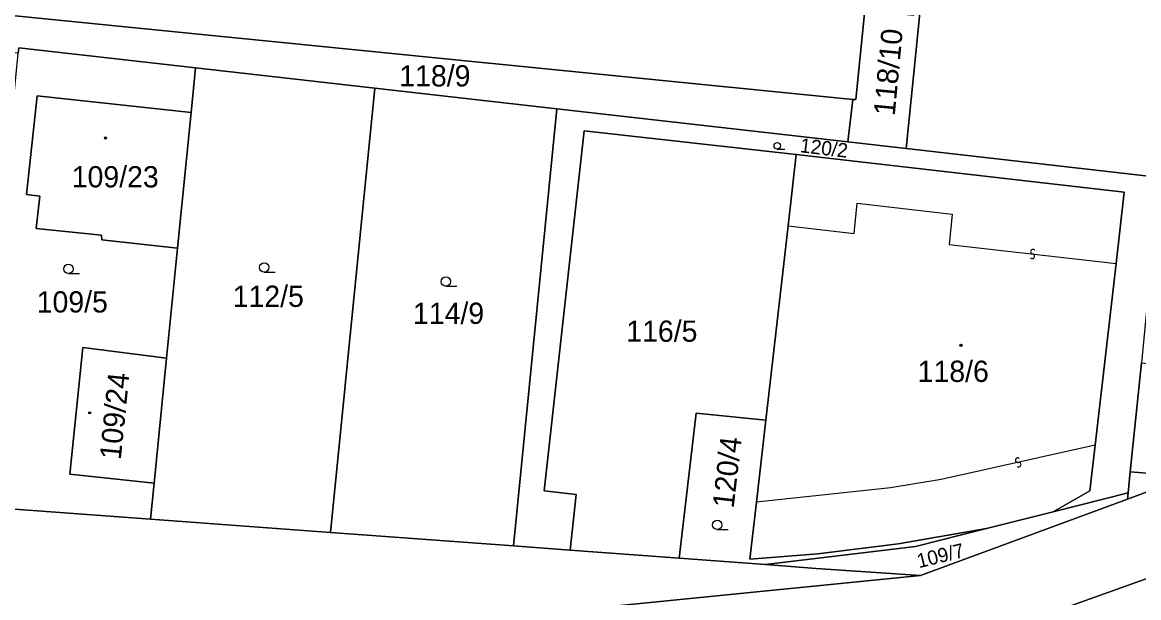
# Model space of a CAD drawing. Extents: x -598233 to -596890, y -1157848 to -1156431.
# Drawn here: x -597800.5 to -597711.3, y -1156974 to -1156928 of the extents above; entities that cross this region are included whole.
import ezdxf

# ---------------------------------------------------------------- set-up
doc = ezdxf.new("R2010")
doc.units = 0
for name, color, linetype in [('Level 1', 7, 'Continuous'), ('Level 13', 7, 'Continuous'), ('Level 3', 7, 'Continuous'), ('Level 4', 7, 'Continuous'), ('Level 5', 7, 'Continuous'), ('Level 60', 7, 'Continuous')]:
    doc.layers.add(name, color=color, linetype=linetype)

msp = doc.modelspace()

# ---------------------------------------------------------------- linework, layer by layer
at = {"layer": 'Level 1'}
for points in [[(-597727.02, -1156909.5), (-597729.1, -1156930.44), (-597729.86, -1156938.05)], [(-597734.12, -1156934.12), (-597811.53, -1156926.41)], [(-597733.17, -1156927), (-597733.89, -1156934.14), (-597734.12, -1156934.12)], [(-597786.67, -1156931.6), (-597800.79, -1156930), (-597800.83, -1156930.42)], [(-597786.67, -1156931.6), (-597787.02, -1156935.17)], [(-597772.34, -1156933.23), (-597786.67, -1156931.6)], [(-597775.87, -1156968.75), (-597772.34, -1156933.23)], [(-597757.78, -1156934.88), (-597772.34, -1156933.23)], [(-597788.1, -1156946.01), (-597794.16, -1156945.36), (-597794.17, -1156944.98), (-597799.41, -1156944.45), (-597799.11, -1156941.86), (-597800.18, -1156941.72), (-597799.33, -1156933.85), (-597787.02, -1156935.17)], [(-597734.12, -1156934.12), (-597734.53, -1156937.52)], [(-597787.02, -1156935.17), (-597788.1, -1156946.01)], [(-597757.78, -1156934.88), (-597761.25, -1156969.82)], [(-597734.53, -1156937.52), (-597757.78, -1156934.88)], [(-597738.67, -1156938.54), (-597755.61, -1156936.64), (-597758.79, -1156965.41), (-597756.25, -1156965.7), (-597756.73, -1156970.15)], [(-597734.53, -1156937.52), (-597729.86, -1156938.05)], [(-597740.42, -1156982.59), (-597736.99, -1156981.86), (-597702.06, -1156969.37), (-597691.71, -1156965.31), (-597650.91, -1156948.42), (-597627.87, -1156938.26)], [(-597738.67, -1156938.54), (-597739.31, -1156944.24)], [(-597713.09, -1156947.25), (-597712.44, -1156941.54), (-597738.67, -1156938.54)], [(-597709.57, -1156940.36), (-597729.86, -1156938.05)], [(-597739.31, -1156944.24), (-597741.07, -1156959.76)], [(-597788.1, -1156946.01), (-597788.97, -1156954.81)], [(-597714.75, -1156961.76), (-597713.09, -1156947.25)], [(-597789.96, -1156964.79), (-597796.72, -1156964.08), (-597795.67, -1156953.97), (-597788.97, -1156954.81)], [(-597788.97, -1156954.81), (-597789.96, -1156964.79)], [(-597711.96, -1156963.9), (-597711.07, -1156955.17)], [(-597748.02, -1156970.8), (-597746.64, -1156959.21), (-597741.07, -1156959.76)], [(-597741.07, -1156959.76), (-597741.83, -1156966.31)], [(-597718.13, -1156967.08), (-597715.18, -1156965.42), (-597714.75, -1156961.76)], [(-597712.13, -1156965.57), (-597711.96, -1156963.9)], [(-597711.96, -1156963.9), (-597707.29, -1156964.27)], [(-597789.96, -1156964.79), (-597790.25, -1156967.68)], [(-597712.18, -1156966.07), (-597707.29, -1156964.27)], [(-597718.13, -1156967.08), (-597712.13, -1156965.57)], [(-597712.18, -1156966.07), (-597712.13, -1156965.57)], [(-597741.83, -1156966.31), (-597742.35, -1156970.87), (-597736.93, -1156970.45), (-597730.5, -1156969.64), (-597723.45, -1156968.43)], [(-597728.72, -1156972.17), (-597712.18, -1156966.07)], [(-597804.41, -1156966.64), (-597790.25, -1156967.68)], [(-597723.45, -1156968.43), (-597718.13, -1156967.08)], [(-597790.25, -1156967.68), (-597775.87, -1156968.75)], [(-597775.87, -1156968.75), (-597761.25, -1156969.82)], [(-597741.12, -1156971.31), (-597729.13, -1156969.86), (-597723.45, -1156968.43)], [(-597761.25, -1156969.82), (-597756.73, -1156970.15)], [(-597756.73, -1156970.15), (-597748.02, -1156970.8)], [(-597748.02, -1156970.8), (-597741.12, -1156971.31)], [(-597728.72, -1156972.17), (-597737.05, -1156971.61), (-597741.12, -1156971.31)], [(-597728.72, -1156972.17), (-597771.93, -1156976.51), (-597816.86, -1156986.47), (-597833.49, -1156992.82)]]:
    msp.add_lwpolyline(points, dxfattribs=at)
at = {"layer": 'Level 13'}
for centre, start, end in [((-597719.782, -1156946.663), 210.62032, 83.21032), ((-597719.737, -1156946.297), 30.83478, 262.93277), ((-597720.949, -1156962.96), 49.74124, 282.33124), ((-597720.871, -1156963.32), 229.9557, 102.05369)]:
    msp.add_arc(centre, 0.184, start, end, dxfattribs=at)
at = {"layer": 'Level 3'}
for points in [[(-597739.31, -1156944.24), (-597734.03, -1156944.85), (-597733.78, -1156942.41), (-597726.18, -1156943.29), (-597726.44, -1156945.72), (-597713.09, -1156947.25)], [(-597714.75, -1156961.76), (-597727.07, -1156964.51), (-597731.12, -1156965.18), (-597741.83, -1156966.31)]]:
    msp.add_lwpolyline(points, dxfattribs=at)
at = {"layer": 'Level 5'}
for p, q in [((-597740.17, -1156938.09), (-597739.575, -1156938.09)), ((-597796.82, -1156948.05), (-597795.945, -1156948.05)), ((-597781.17, -1156947.93), (-597780.295, -1156947.93)), ((-597766.65, -1156949.06), (-597765.775, -1156949.06)), ((-597744.97, -1156968.51), (-597744.095, -1156968.51))]:
    msp.add_line(p, q, dxfattribs=at)
for centre, radius in [((-597793.86, -1156937.22), 0.09), ((-597793.86, -1156937.22), 0.0521), ((-597740.17, -1156937.835), 0.255), ((-597796.82, -1156947.675), 0.375), ((-597781.17, -1156947.555), 0.375), ((-597766.65, -1156948.685), 0.375), ((-597725.49, -1156953.78), 0.09), ((-597725.49, -1156953.78), 0.0521), ((-597795.13, -1156959.18), 0.09), ((-597795.13, -1156959.18), 0.0521), ((-597744.97, -1156968.135), 0.375)]:
    msp.add_circle(centre, radius, dxfattribs=at)
at = {"layer": 'Level 60'}
for points in [[(-597728.06, -1156901.77), (-597726.35, -1156886.79), (-597702.27, -1156890.36), (-597704.74, -1156904.94), (-597709.45, -1156932.7), (-597709.6, -1156933.62), (-597708.92, -1156933.7), (-597709.57, -1156940.36), (-597729.86, -1156938.05), (-597729.1, -1156930.44), (-597727.02, -1156909.5), (-597728.59, -1156906.36)], [(-597732.9, -1156924.28), (-597733.17, -1156927), (-597733.89, -1156934.14), (-597734.12, -1156934.12), (-597811.53, -1156926.41), (-597810.33, -1156914.08), (-597809.92, -1156909.87), (-597809.33, -1156903.87), (-597801.85, -1156904.61), (-597796.06, -1156905.19), (-597771.57, -1156907.63), (-597765.37, -1156908.24), (-597744.95, -1156910.27), (-597739.08, -1156910.86), (-597731.63, -1156911.6)], [(-597727.36, -1156909.46), (-597727.02, -1156909.5), (-597729.1, -1156930.44), (-597729.86, -1156938.05), (-597734.53, -1156937.52), (-597734.12, -1156934.12), (-597733.89, -1156934.14), (-597733.17, -1156927), (-597729.26, -1156927.4)], [(-597734.12, -1156934.12), (-597734.53, -1156937.52), (-597757.78, -1156934.88), (-597772.34, -1156933.23), (-597786.67, -1156931.6), (-597800.79, -1156930), (-597800.83, -1156930.42), (-597811.77, -1156929.19), (-597811.53, -1156926.41)], [(-597804.41, -1156966.64), (-597803.42, -1156956.64), (-597802.31, -1156945.39), (-597801.78, -1156940.03), (-597800.86, -1156930.73), (-597800.83, -1156930.42), (-597800.79, -1156930), (-597786.67, -1156931.6), (-597787.02, -1156935.17), (-597799.33, -1156933.85), (-597800.18, -1156941.72), (-597799.11, -1156941.86), (-597799.41, -1156944.45), (-597794.17, -1156944.98), (-597794.16, -1156945.36), (-597788.1, -1156946.01), (-597788.97, -1156954.81), (-597795.67, -1156953.97), (-597796.72, -1156964.08), (-597789.96, -1156964.79), (-597790.25, -1156967.68)], [(-597772.34, -1156933.23), (-597775.87, -1156968.75), (-597790.25, -1156967.68), (-597789.96, -1156964.79), (-597788.97, -1156954.81), (-597788.1, -1156946.01), (-597787.02, -1156935.17), (-597786.67, -1156931.6)], [(-597775.87, -1156968.75), (-597772.34, -1156933.23), (-597757.78, -1156934.88), (-597761.25, -1156969.82)], [(-597788.1, -1156946.01), (-597794.16, -1156945.36), (-597794.17, -1156944.98), (-597799.41, -1156944.45), (-597799.11, -1156941.86), (-597800.18, -1156941.72), (-597799.33, -1156933.85), (-597787.02, -1156935.17)], [(-597734.53, -1156937.52), (-597729.86, -1156938.05), (-597709.57, -1156940.36), (-597709.61, -1156940.78), (-597709.64, -1156941.08), (-597710.54, -1156949.91), (-597711.07, -1156955.17), (-597711.96, -1156963.9), (-597712.13, -1156965.57), (-597718.13, -1156967.08), (-597715.18, -1156965.42), (-597714.75, -1156961.76), (-597713.09, -1156947.25), (-597712.44, -1156941.54), (-597738.67, -1156938.54), (-597755.61, -1156936.64), (-597758.79, -1156965.41), (-597756.25, -1156965.7), (-597756.73, -1156970.15), (-597761.25, -1156969.82), (-597757.78, -1156934.88)], [(-597755.61, -1156936.64), (-597738.67, -1156938.54), (-597739.31, -1156944.24), (-597741.07, -1156959.76), (-597746.64, -1156959.21), (-597748.02, -1156970.8), (-597756.73, -1156970.15), (-597756.25, -1156965.7), (-597758.79, -1156965.41)], [(-597741.83, -1156966.31), (-597741.07, -1156959.76), (-597739.31, -1156944.24), (-597738.67, -1156938.54), (-597712.44, -1156941.54), (-597713.09, -1156947.25), (-597714.75, -1156961.76), (-597715.18, -1156965.42), (-597718.13, -1156967.08), (-597723.45, -1156968.43), (-597730.5, -1156969.64), (-597736.93, -1156970.45), (-597742.35, -1156970.87)], [(-597724.24, -1156983.99), (-597740.42, -1156982.59), (-597736.99, -1156981.86), (-597702.06, -1156969.37), (-597691.71, -1156965.31), (-597650.91, -1156948.42), (-597627.87, -1156938.26), (-597625.42, -1156944.15), (-597631.15, -1156946.24), (-597674.44, -1156965.28), (-597682.05, -1156968.14), (-597698.03, -1156974.14)], [(-597789.96, -1156964.79), (-597796.72, -1156964.08), (-597795.67, -1156953.97), (-597788.97, -1156954.81)], [(-597695.18, -1156956.87), (-597688.99, -1156957.53), (-597707.29, -1156964.27), (-597711.96, -1156963.9), (-597711.07, -1156955.17)], [(-597748.02, -1156970.8), (-597746.64, -1156959.21), (-597741.07, -1156959.76), (-597741.83, -1156966.31), (-597742.35, -1156970.87), (-597736.93, -1156970.45), (-597730.5, -1156969.64), (-597723.45, -1156968.43), (-597729.13, -1156969.86), (-597741.12, -1156971.31)], [(-597711.96, -1156963.9), (-597707.29, -1156964.27), (-597712.18, -1156966.07), (-597712.13, -1156965.57)], [(-597712.13, -1156965.57), (-597712.18, -1156966.07), (-597728.72, -1156972.17), (-597737.05, -1156971.61), (-597741.12, -1156971.31), (-597729.13, -1156969.86), (-597723.45, -1156968.43), (-597718.13, -1156967.08)]]:
    msp.add_lwpolyline(points, close=True, dxfattribs=at)
for points in [[(-598001.49, -1156961.77), (-597839.67, -1156973.77), (-597829.53, -1156972.01), (-597829.24, -1156968.46), (-597829.05, -1156966.34), (-597839.08, -1156965.6), (-597840.87, -1156965.06), (-597841.91, -1156963.76), (-597810.8, -1156966.17), (-597804.41, -1156966.64), (-597790.25, -1156967.68), (-597775.87, -1156968.75), (-597761.25, -1156969.82), (-597756.73, -1156970.15), (-597748.02, -1156970.8), (-597741.12, -1156971.31), (-597737.05, -1156971.61), (-597728.72, -1156972.17), (-597771.93, -1156976.51), (-597816.86, -1156986.47), (-597833.49, -1156992.82), (-597918.66, -1156993.37)], [(-597869.1, -1157006.41), (-597833.49, -1156992.82), (-597816.86, -1156986.47), (-597771.93, -1156976.51), (-597728.72, -1156972.17), (-597712.18, -1156966.07), (-597707.29, -1156964.27)], [(-597702.06, -1156969.37), (-597736.99, -1156981.86), (-597740.42, -1156982.59), (-597751.55, -1156984.95), (-597769.34, -1156988.73), (-597787.11, -1156992.51), (-597804.87, -1156996.28), (-597809.83, -1156998.38), (-597830.94, -1157007.32), (-597831.4, -1157006.17), (-597849.66, -1157013.81)]]:
    msp.add_lwpolyline(points, dxfattribs=at)

# ---------------------------------------------------------------- texts
at = {"layer": 'Level 4'}
for s, height, rotation, p in [('118/10', 1.7, 84.6, (-597730.784, -1156935.481)), ('120/2', 1.14, 353.169, (-597738.394, -1156938.342)), ('109/24', 1.7, 84.22569, (-597792.638, -1156962.977)), ('120/4', 1.7, 83.40003, (-597743.66, -1156966.85)), ('109/7', 1.14, 13.87089, (-597728.844, -1156971.603))]:
    msp.add_text(s, height=height, rotation=rotation, dxfattribs=at).set_placement(p)
for s, p in [('118/9', (-597770.379, -1156933.09)), ('109/23', (-597796.556, -1156941.16)), ('109/5', (-597799.357, -1156951.16)), ('112/5', (-597783.691, -1156950.71)), ('114/9', (-597769.285, -1156952.07)), ('116/5', (-597752.236, -1156953.5)), ('118/6', (-597728.949, -1156956.71))]:
    msp.add_text(s, height=1.7, dxfattribs=at).set_placement(p)

doc.saveas('drawing.dxf')
